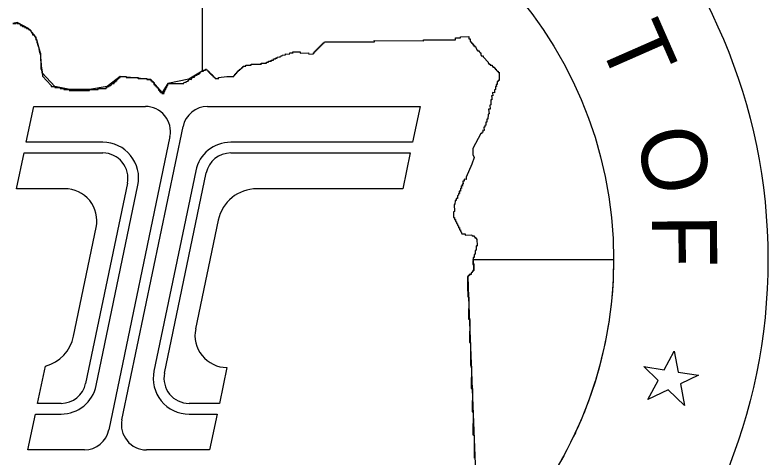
# Model space of a CAD drawing. Extents: x 0 to 1.42, y 0 to 0.92.
# Drawn here: x 1.34592 to 1.37918, y 0.0954 to 0.11497 of the extents above; entities that cross this region are included whole.
import ezdxf

# ---------------------------------------------------------------- set-up
doc = ezdxf.new("R2010")
doc.units = 0
doc.layers.add('P_ODOT_PLAN_TBlock', color=7, linetype='Continuous')

msp = doc.modelspace()

# ---------------------------------------------------------------- linework, layer by layer
at = {"layer": 'P_ODOT_PLAN_TBlock'}
for p, q in [((1.346415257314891, 0.10934955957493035), (1.3467444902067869, 0.11092977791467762)), ((1.3467444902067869, 0.11092977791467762), (1.3516792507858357, 0.11092977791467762)), ((1.35442335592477, 0.11092977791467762), (1.363810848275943, 0.11092977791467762)), ((1.363810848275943, 0.11092977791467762), (1.363481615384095, 0.10934955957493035)), ((1.3506409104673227, 0.09709142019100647), (1.3533404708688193, 0.11004921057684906)), ((1.3527621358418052, 0.10959803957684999), (1.3500626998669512, 0.09664024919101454)), ((1.3497985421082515, 0.10934955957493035), (1.346415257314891, 0.10934955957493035)), ((1.363481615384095, 0.10934955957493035), (1.3554480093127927, 0.10934955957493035)), ((1.345987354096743, 0.10729527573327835), (1.3463165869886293, 0.10887549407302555)), ((1.3463165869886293, 0.10887549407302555), (1.3497985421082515, 0.10887549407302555)), ((1.3554481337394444, 0.10887549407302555), (1.3633828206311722, 0.10887549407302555)), ((1.3633828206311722, 0.10887549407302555), (1.363053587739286, 0.10729527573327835)), ((1.3539010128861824, 0.10809160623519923), (1.352057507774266, 0.09924238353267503)), ((1.3525216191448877, 0.09914570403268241), (1.3543652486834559, 0.10799492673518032)), ((1.3508814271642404, 0.10754375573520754), (1.3490379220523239, 0.09869453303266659)), ((1.3495020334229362, 0.09859785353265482), (1.3513455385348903, 0.10744707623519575)), ((1.3481121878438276, 0.10729527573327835), (1.345987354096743, 0.10729527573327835)), ((1.3481121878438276, 0.10729527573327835), (1.3481121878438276, 0.10729527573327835)), ((1.363053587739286, 0.10729527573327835), (1.3566013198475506, 0.10729527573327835)), ((1.354899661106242, 0.10591152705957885), (1.3538985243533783, 0.10110641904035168)), ((1.3485035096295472, 0.1007779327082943), (1.3495045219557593, 0.10558304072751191)), ((1.3469175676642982, 0.09781396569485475), (1.3472601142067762, 0.09945826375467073)), ((1.3552745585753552, 0.09939754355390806), (1.3549445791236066, 0.09781396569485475)), ((1.3479550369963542, 0.09781396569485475), (1.3469175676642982, 0.09781396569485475)), ((1.3549445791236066, 0.09781396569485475), (1.353604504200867, 0.09781396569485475)), ((1.3464895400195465, 0.09575968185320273), (1.346818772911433, 0.09733990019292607)), ((1.346818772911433, 0.09733990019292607), (1.3479550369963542, 0.09733990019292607)), ((1.353604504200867, 0.09733990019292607), (1.354845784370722, 0.09733990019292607)), ((1.354845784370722, 0.09733990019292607), (1.3545166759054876, 0.09575968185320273)), ((1.3489798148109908, 0.09575968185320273), (1.3464895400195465, 0.09575968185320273)), ((1.3545166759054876, 0.09575968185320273), (1.351723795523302, 0.09575968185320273))]:
    msp.add_line(p, q, dxfattribs=at)
for points in [[(1.3541833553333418, 0.1223454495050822), (1.3541869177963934, 0.1124870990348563), (1.3535949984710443, 0.11213001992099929), (1.3526673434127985, 0.11194921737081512), (1.3524210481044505, 0.11154263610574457), (1.3519121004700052, 0.11212601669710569), (1.3505598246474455, 0.11226013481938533), (1.3499846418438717, 0.11181019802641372), (1.3492117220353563, 0.11167553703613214), (1.348332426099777, 0.11167616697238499), (1.3476754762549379, 0.11181117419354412), (1.3471190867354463, 0.11242080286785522), (1.3470410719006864, 0.11329283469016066), (1.3468748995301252, 0.11387543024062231), (1.346757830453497, 0.1141006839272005), (1.3465189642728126, 0.11436991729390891), (1.3460096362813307, 0.11463941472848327), (1.3458199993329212, 0.1145945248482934)], [(1.3458199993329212, 0.1145945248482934), (1.3459421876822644, 0.11459434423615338), (1.345973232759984, 0.1145932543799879), (1.345973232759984, 0.11463856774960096), (1.3460096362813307, 0.11463941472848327), (1.3460117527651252, 0.11459237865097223), (1.3461239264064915, 0.11459410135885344), (1.3461239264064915, 0.11455110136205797), (1.346162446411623, 0.114550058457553), (1.3461615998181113, 0.11450468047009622), (1.3462373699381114, 0.11450389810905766), (1.3462428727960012, 0.11445858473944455), (1.3463529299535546, 0.11445816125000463), (1.3463394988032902, 0.11441496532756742), (1.3464296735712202, 0.11441502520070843), (1.3464279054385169, 0.11437162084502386), (1.3465189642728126, 0.11436991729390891), (1.3465196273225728, 0.11432449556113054), (1.3465642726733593, 0.11432480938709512), (1.3466109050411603, 0.11428059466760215), (1.3466122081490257, 0.11423561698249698), (1.3466480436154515, 0.1142346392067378), (1.3466477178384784, 0.11418755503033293), (1.346684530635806, 0.11419031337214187), (1.346684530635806, 0.114097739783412), (1.346757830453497, 0.1141006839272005), (1.3467584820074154, 0.1140557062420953), (1.3467936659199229, 0.1140553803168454), (1.3467936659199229, 0.11401117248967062), (1.3468295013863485, 0.11401082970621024), (1.3468402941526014, 0.11387577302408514), (1.3468748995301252, 0.11387543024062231), (1.346874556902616, 0.11374140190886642), (1.3468967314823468, 0.11374018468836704), (1.3469178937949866, 0.11360750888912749), (1.346954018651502, 0.11358414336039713), (1.3470019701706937, 0.11329321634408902), (1.3470410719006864, 0.11329283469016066), (1.3470543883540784, 0.11257532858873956), (1.3471023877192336, 0.11257532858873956), (1.347135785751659, 0.1122662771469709), (1.3475182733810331, 0.11185584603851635), (1.3475204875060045, 0.11181154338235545), (1.3476754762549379, 0.11181117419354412), (1.3476762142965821, 0.11176752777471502), (1.3479095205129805, 0.11176664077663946), (1.347912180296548, 0.11172229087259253), (1.348078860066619, 0.11172051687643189), (1.3480797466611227, 0.11167616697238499), (1.348332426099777, 0.11167616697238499), (1.348315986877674, 0.1116298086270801), (1.3491886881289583, 0.11163307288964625), (1.3492099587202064, 0.11163143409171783), (1.3492117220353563, 0.11167553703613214), (1.3495955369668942, 0.1116796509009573), (1.3495943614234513, 0.11172199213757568), (1.3499399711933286, 0.11172434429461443), (1.3499382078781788, 0.11176962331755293), (1.3499817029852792, 0.11176727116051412), (1.3499846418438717, 0.11181019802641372), (1.350070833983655, 0.11181372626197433), (1.3500704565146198, 0.11185488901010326), (1.350153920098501, 0.11185724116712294), (1.3501586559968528, 0.11190094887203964), (1.3502002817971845, 0.11190198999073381), (1.3502002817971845, 0.11194467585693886), (1.350290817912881, 0.11194519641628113), (1.3502897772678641, 0.11199152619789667), (1.350332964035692, 0.11199152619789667), (1.3503334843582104, 0.11203421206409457), (1.3503829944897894, 0.11204095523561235), (1.350380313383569, 0.11208002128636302), (1.3504240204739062, 0.11208158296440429), (1.3504219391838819, 0.11212687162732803), (1.3504698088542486, 0.11212999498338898), (1.3504698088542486, 0.11217216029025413), (1.3505127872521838, 0.11217370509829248), (1.3505129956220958, 0.11221588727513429), (1.3505557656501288, 0.11221741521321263), (1.3505598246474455, 0.11226013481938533), (1.3508301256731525, 0.11225746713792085), (1.350827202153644, 0.11221505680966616), (1.3513651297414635, 0.11221505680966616), (1.3513629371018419, 0.11216899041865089), (1.3517429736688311, 0.11216899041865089), (1.3517455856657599, 0.11212292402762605), (1.3519121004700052, 0.11212601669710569), (1.3519094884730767, 0.11208093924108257), (1.3519591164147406, 0.11208289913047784), (1.3519525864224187, 0.1120332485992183), (1.352016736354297, 0.1120365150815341), (1.3520156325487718, 0.11199208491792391), (1.3520581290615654, 0.1119894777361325), (1.3520570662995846, 0.11190128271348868), (1.3520989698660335, 0.11190128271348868), (1.352097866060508, 0.1118562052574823), (1.3521409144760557, 0.1118568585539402), (1.3521432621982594, 0.11181236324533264), (1.3521800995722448, 0.11180720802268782), (1.3521817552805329, 0.11176539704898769), (1.3522220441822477, 0.11176997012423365), (1.3522198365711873, 0.11172423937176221), (1.3522628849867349, 0.1117170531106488), (1.3522614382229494, 0.11164577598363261), (1.3522955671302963, 0.1116325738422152), (1.3522995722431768, 0.1115932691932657), (1.3523405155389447, 0.11158854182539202), (1.3523377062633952, 0.11154076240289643), (1.3524210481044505, 0.11154263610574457), (1.3524095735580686, 0.11149757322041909), (1.3525015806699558, 0.11150141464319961), (1.3524843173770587, 0.11158792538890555), (1.3525352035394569, 0.1115977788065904), (1.3525302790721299, 0.11167742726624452), (1.3525754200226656, 0.11168071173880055), (1.3525754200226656, 0.11176939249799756), (1.3526213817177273, 0.11177267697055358), (1.352622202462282, 0.11185889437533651), (1.3526681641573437, 0.11186299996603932), (1.3526673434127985, 0.11194921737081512), (1.353369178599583, 0.11194641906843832), (1.3533879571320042, 0.11199766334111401), (1.3534807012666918, 0.11199437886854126), (1.3534765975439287, 0.11203625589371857), (1.3535660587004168, 0.11204118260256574), (1.3535505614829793, 0.1120827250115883), (1.3535940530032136, 0.11208512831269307), (1.3535949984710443, 0.11213001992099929), (1.3537207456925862, 0.11212907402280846), (1.3537131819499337, 0.11216785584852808), (1.3537477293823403, 0.11217636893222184), (1.3537444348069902, 0.11221988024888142), (1.3538427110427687, 0.11222082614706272), (1.3538436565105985, 0.11225771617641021), (1.3538814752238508, 0.11226826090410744), (1.353882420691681, 0.11230501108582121), (1.3539665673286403, 0.1123156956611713), (1.3539684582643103, 0.1123523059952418), (1.3540461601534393, 0.11235325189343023), (1.354050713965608, 0.11239581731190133), (1.3540904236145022, 0.11240338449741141), (1.3540960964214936, 0.11245257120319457), (1.3541906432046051, 0.1124885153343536), (1.3542435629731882, 0.11248696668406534), (1.3542394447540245, 0.11253063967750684), (1.3543325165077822, 0.1125322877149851), (1.3543308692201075, 0.11257513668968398), (1.3543761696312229, 0.11257596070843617), (1.3543854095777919, 0.11253864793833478), (1.3544247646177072, 0.11252981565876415), (1.3544307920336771, 0.1124904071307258), (1.3544733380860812, 0.11248756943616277), (1.35446955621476, 0.1124412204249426), (1.3545130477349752, 0.11243932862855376), (1.3545121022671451, 0.1123996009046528), (1.3545527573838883, 0.11239487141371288), (1.35455937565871, 0.11235325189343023), (1.3546092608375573, 0.11235136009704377), (1.3546038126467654, 0.11231352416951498), (1.3546504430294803, 0.11230690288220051), (1.3546520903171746, 0.11226149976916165), (1.3546949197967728, 0.11226055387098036), (1.3546957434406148, 0.11222082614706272), (1.3547385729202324, 0.1122160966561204), (1.3547535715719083, 0.11217172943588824), (1.3549156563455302, 0.11217054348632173), (1.3549131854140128, 0.11221751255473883), (1.3552741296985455, 0.11226029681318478), (1.3555915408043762, 0.11226029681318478), (1.3555934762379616, 0.11230676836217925), (1.3556307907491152, 0.11230483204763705), (1.3556315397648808, 0.1123519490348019), (1.3556698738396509, 0.11235130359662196), (1.3556728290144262, 0.11239648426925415), (1.3557134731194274, 0.11239777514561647), (1.3557115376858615, 0.1124410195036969), (1.3557534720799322, 0.11244295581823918), (1.3557502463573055, 0.11248555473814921), (1.3557947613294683, 0.11248942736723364), (1.3557941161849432, 0.11252944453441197), (1.3558516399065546, 0.11253267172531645), (1.3558516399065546, 0.11257591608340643), (1.355892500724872, 0.11257623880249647), (1.355913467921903, 0.11261980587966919), (1.3559534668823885, 0.1126223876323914), (1.355950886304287, 0.11266692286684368), (1.3559960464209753, 0.11266498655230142), (1.3559934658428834, 0.11271016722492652), (1.356110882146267, 0.11271210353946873), (1.3561153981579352, 0.11275470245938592), (1.3563551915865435, 0.11275663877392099), (1.3563551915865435, 0.11280039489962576), (1.3568013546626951, 0.11279927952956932), (1.3567995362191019, 0.11284567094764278), (1.3570219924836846, 0.11284567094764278), (1.35702381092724, 0.11288842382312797), (1.3571126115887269, 0.11288993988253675), (1.357113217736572, 0.11293481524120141), (1.3572471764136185, 0.11293693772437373), (1.357241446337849, 0.1129823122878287), (1.3573349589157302, 0.11298217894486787), (1.3573323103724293, 0.11302816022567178), (1.3574227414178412, 0.1130274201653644), (1.3574168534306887, 0.11307163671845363), (1.3575039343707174, 0.11306926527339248), (1.3575053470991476, 0.1131159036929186), (1.357644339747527, 0.11312027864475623), (1.3576349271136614, 0.11315938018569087), (1.35772579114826, 0.11316254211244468), (1.357720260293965, 0.1132044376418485), (1.3578741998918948, 0.11320958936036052), (1.3578664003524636, 0.11325445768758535), (1.3580475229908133, 0.11324665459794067), (1.3580518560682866, 0.11329867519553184), (1.3581999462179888, 0.1133059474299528), (1.3581982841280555, 0.11333802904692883), (1.3582581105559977, 0.11333942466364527), (1.3585102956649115, 0.11334115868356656), (1.3585163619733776, 0.11329090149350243), (1.358890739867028, 0.11329867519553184), (1.3588942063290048, 0.11324318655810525), (1.3590991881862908, 0.11324958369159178), (1.3590978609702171, 0.11329867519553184), (1.3591420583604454, 0.11329520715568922), (1.359140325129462, 0.11334636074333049), (1.3591819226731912, 0.11334115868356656), (1.3591827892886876, 0.11338711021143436), (1.3592287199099, 0.11338537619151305), (1.3592209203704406, 0.1134304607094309), (1.3592711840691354, 0.11343219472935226), (1.3592670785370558, 0.11347311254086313), (1.3593156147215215, 0.11347630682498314), (1.3593099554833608, 0.11351801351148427), (1.3593600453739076, 0.11352041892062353), (1.3593572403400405, 0.11356451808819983), (1.3594045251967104, 0.11356612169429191), (1.3594021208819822, 0.11360821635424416), (1.3594490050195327, 0.113609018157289), (1.3594466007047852, 0.11365271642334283), (1.3594926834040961, 0.11365351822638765), (1.3594926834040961, 0.11369801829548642), (1.3595371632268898, 0.11369801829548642), (1.3595371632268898, 0.11374251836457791), (1.3595824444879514, 0.11374251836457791), (1.359586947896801, 0.11378814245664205), (1.3618019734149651, 0.11378082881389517), (1.3617847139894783, 0.11384080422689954), (1.3639848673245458, 0.11383658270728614), (1.3639719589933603, 0.11387819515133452), (1.365377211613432, 0.11387617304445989), (1.365378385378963, 0.11396453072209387), (1.3655975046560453, 0.11396701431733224), (1.3655949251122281, 0.11401295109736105), (1.3659632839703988, 0.11401638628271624), (1.3659627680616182, 0.1139232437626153), (1.366025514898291, 0.11392533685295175), (1.3660234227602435, 0.11379765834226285), (1.3660642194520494, 0.11378614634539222), (1.3660782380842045, 0.11374114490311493), (1.3661144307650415, 0.11374428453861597), (1.3661188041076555, 0.11369509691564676), (1.3661531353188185, 0.11369928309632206), (1.366147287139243, 0.11365323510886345), (1.3661939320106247, 0.1136553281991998), (1.366171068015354, 0.11360963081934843), (1.3661827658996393, 0.11361032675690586), (1.3662378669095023, 0.11361032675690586), (1.3662338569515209, 0.11356113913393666), (1.3662776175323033, 0.11356323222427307), (1.366284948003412, 0.11347322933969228), (1.3663137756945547, 0.11347458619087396), (1.3663166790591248, 0.113428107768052), (1.3663511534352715, 0.11343101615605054), (1.3663484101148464, 0.11338298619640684), (1.3664238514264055, 0.11338538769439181), (1.3664207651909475, 0.113337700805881), (1.3664584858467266, 0.11333804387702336), (1.3664631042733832, 0.11329584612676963), (1.3664962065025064, 0.11329447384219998), (1.366501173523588, 0.11320298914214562), (1.3665347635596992, 0.11320414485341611), (1.3665342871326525, 0.11315918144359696), (1.366600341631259, 0.11316178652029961), (1.3665993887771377, 0.1131163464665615), (1.3666207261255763, 0.11311353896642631), (1.3668241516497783, 0.11288765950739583), (1.3668227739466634, 0.11284447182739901), (1.366856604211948, 0.11284523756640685), (1.366856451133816, 0.11280005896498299), (1.3669127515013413, 0.11280098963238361), (1.366916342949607, 0.11275607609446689), (1.3669957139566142, 0.11275643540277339), (1.3669942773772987, 0.11270872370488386), (1.3670327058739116, 0.11271331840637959), (1.3670327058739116, 0.11266804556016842), (1.367096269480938, 0.11266798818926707), (1.3670960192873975, 0.11261971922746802), (1.3671332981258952, 0.11262168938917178), (1.3671317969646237, 0.11257455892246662), (1.367171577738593, 0.11257505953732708), (1.3671695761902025, 0.112529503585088), (1.3672068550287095, 0.11253106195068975), (1.3672211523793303, 0.11248476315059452), (1.3672654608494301, 0.11248771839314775), (1.367269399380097, 0.1124364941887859), (1.3673117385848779, 0.1124394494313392), (1.3673117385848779, 0.11207693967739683), (1.367259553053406, 0.11207890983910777), (1.3672605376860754, 0.11202965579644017), (1.3672162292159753, 0.11203655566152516), (1.3672191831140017, 0.1118986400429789), (1.3671719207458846, 0.11190356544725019), (1.3671876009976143, 0.11180899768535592), (1.3671507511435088, 0.11180899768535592), (1.3671440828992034, 0.11167461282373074), (1.3671041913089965, 0.11166735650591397), (1.3671005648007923, 0.1115381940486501), (1.3670186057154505, 0.11154254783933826), (1.3670222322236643, 0.11140540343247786), (1.366973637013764, 0.11139959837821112), (1.366984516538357, 0.11130599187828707), (1.3669816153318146, 0.11122399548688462), (1.3669344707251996, 0.11122617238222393), (1.3669341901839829, 0.11100103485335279), (1.366889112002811, 0.1109943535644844), (1.3669091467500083, 0.11081729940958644), (1.366842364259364, 0.11081562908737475), (1.3668674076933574, 0.1106001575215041), (1.3668217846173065, 0.1105951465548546), (1.366812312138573, 0.11036631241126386), (1.3667689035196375, 0.11037132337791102), (1.3667622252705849, 0.11023769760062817), (1.3667171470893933, 0.11023769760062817), (1.3667221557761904, 0.11010073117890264), (1.3666737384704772, 0.11009572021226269), (1.3666737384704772, 0.110008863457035), (1.3666370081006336, 0.110008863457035), (1.3666386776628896, 0.109875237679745), (1.3665902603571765, 0.10988525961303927), (1.366591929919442, 0.10979172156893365), (1.366546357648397, 0.10977835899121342), (1.3665451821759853, 0.10974161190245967), (1.3664934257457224, 0.10974161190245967), (1.3661470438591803, 0.10907334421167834), (1.3661470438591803, 0.10881403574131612), (1.3662092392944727, 0.10866882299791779), (1.366105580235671, 0.10837839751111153), (1.365853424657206, 0.10781130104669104), (1.3658548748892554, 0.1077097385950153), (1.3657671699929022, 0.10772569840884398), (1.3657649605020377, 0.10763284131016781), (1.36570840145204, 0.10763284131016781), (1.3657229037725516, 0.10750226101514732), (1.3656750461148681, 0.10749645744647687), (1.365680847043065, 0.10741520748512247), (1.3656300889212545, 0.10741810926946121), (1.3656387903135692, 0.10731219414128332), (1.3655954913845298, 0.10732525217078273), (1.365598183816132, 0.10718161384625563), (1.3655474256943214, 0.1071830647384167), (1.365554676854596, 0.10708730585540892), (1.3655111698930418, 0.10708427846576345), (1.365506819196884, 0.10700605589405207), (1.3654633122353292, 0.10698429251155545), (1.3654618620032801, 0.10686822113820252), (1.365412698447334, 0.10686822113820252), (1.3654033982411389, 0.10678261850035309), (1.365363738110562, 0.1067764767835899), (1.3653548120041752, 0.10660159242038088), (1.3653196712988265, 0.10659719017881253), (1.3653390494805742, 0.10629060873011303), (1.365290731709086, 0.10627587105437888), (1.3652864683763, 0.10602474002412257), (1.3653376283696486, 0.10602616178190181), (1.365336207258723, 0.10593516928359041), (1.3653802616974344, 0.1059323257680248), (1.3653799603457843, 0.10584686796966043), (1.3654271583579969, 0.10583991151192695), (1.3654237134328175, 0.10575856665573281), (1.3654662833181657, 0.10575159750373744), (1.3654639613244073, 0.10566719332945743), (1.3655073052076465, 0.10566099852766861), (1.3655134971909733, 0.10557349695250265), (1.3655491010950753, 0.10557659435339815), (1.3655599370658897, 0.10548676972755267), (1.3655932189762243, 0.10548522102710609), (1.3655932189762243, 0.10540159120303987), (1.365635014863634, 0.10539462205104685), (1.3656512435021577, 0.10530698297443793), (1.3658118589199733, 0.10530521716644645), (1.3658100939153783, 0.10525047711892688), (1.3661030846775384, 0.10526283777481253), (1.3661136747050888, 0.1052204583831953), (1.3662001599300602, 0.1052204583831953), (1.36620368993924, 0.1051763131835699), (1.3662407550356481, 0.10515400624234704), (1.366237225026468, 0.10513169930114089), (1.3662848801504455, 0.1051268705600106), (1.366291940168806, 0.10508272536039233), (1.3663272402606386, 0.10507742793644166), (1.3663325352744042, 0.10476487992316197), (1.366291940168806, 0.10476664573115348), (1.3662937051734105, 0.1045847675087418), (1.3662513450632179, 0.10457417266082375), (1.3662425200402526, 0.10439935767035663), (1.366205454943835, 0.10439623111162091), (1.366205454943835, 0.10426339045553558), (1.3661648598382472, 0.10426162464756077), (1.3661517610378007, 0.1039548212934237), (1.366195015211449, 0.10396046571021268), (1.3661931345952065, 0.10368388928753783), (1.3661508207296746, 0.10368388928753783), (1.3661517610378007, 0.10363779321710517), (1.3661141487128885, 0.10363779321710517), (1.3661103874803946, 0.10359263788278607), (1.3660746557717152, 0.10358678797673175), (1.3660690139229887, 0.10350326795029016), (1.3659872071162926, 0.10350953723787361), (1.3659937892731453, 0.10345811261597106), (1.365944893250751, 0.10345623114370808), (1.3659430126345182, 0.1034138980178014), (1.3659091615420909, 0.10341577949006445), (1.3659145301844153, 0.10300173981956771), (1.3659172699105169, 0.10252206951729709), (1.3659748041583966, 0.102508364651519), (1.365955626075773, 0.10153531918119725), (1.366007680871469, 0.10152161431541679), (1.365992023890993, 0.10049518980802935), (1.3660355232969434, 0.10050389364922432), (1.3660355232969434, 0.09948175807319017), (1.3660842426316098, 0.09946291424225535), (1.3660670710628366, 0.09847609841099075), (1.3661227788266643, 0.09847021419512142), (1.3661203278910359, 0.09743841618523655), (1.3661597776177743, 0.09743653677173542), (1.3661485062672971, 0.09641789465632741), (1.366204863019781, 0.0963915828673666), (1.3661973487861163, 0.0953954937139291)], [(1.3662813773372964, 0.09475265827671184), (1.3659748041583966, 0.102508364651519), (1.3659430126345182, 0.1034138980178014), (1.3661931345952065, 0.10368388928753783), (1.366195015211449, 0.10396046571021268), (1.366160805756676, 0.10416666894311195), (1.3723621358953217, 0.10416666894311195), (1.3723621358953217, 0.10410502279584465), (1.3723621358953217, 0.10399049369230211), (1.3723514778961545, 0.10354586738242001), (1.372343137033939, 0.10333622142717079), (1.3723102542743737, 0.10276577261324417), (1.3722563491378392, 0.10218602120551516), (1.3722485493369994, 0.10207533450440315), (1.3721683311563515, 0.10152062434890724), (1.3721617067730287, 0.10147468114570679), (1.3721618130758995, 0.10147432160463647), (1.3721611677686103, 0.10146936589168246), (1.372150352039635, 0.1013998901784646), (1.3721388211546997, 0.10132640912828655), (1.3721147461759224, 0.10117882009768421), (1.3720970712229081, 0.10107460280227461), (1.3720678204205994, 0.10090914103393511), (1.3720368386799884, 0.1007436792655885), (1.3719958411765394, 0.10053634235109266), (1.3719472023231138, 0.10030554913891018), (1.3718956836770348, 0.10007475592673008), (1.3718212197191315, 0.09976506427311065), (1.3717736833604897, 0.09957910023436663), (1.3717055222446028, 0.09932525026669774), (1.3716391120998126, 0.09909251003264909), (1.3715966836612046, 0.09894732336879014), (1.3715964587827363, 0.0989465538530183), (1.3715941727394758, 0.09893873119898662), (1.371586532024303, 0.0989133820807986), (1.3715217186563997, 0.09870340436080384), (1.3714198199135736, 0.09838987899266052), (1.371299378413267, 0.09804229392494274), (1.3711688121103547, 0.09769127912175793), (1.3710729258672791, 0.09744288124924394), (1.3710150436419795, 0.09729923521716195), (1.3710054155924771, 0.0972756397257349), (1.3709978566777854, 0.09725721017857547), (1.370991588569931, 0.09724197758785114), (1.3709881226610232, 0.0972336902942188), (1.3709876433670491, 0.09723254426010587), (1.3709849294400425, 0.09722584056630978), (1.370972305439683, 0.09719536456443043), (1.3709451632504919, 0.09713097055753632), (1.370811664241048, 0.0968204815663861), (1.3707389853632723, 0.09665809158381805), (1.3706976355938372, 0.09657066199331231), (1.3706741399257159, 0.09651701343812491), (1.370584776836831, 0.09632728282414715), (1.370466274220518, 0.09608390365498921), (1.3703027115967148, 0.09576246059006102), (1.3701531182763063, 0.0954814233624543), (1.37006764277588, 0.09532600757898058)]]:
    msp.add_lwpolyline(points, dxfattribs=at)
msp.add_lwpolyline([(1.3736944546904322, 0.09943832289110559), (1.3745945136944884, 0.09929576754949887), (1.3750436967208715, 0.1001155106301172), (1.3752175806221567, 0.09919708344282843), (1.3761176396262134, 0.09905452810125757), (1.3753172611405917, 0.0986705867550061), (1.3754972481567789, 0.09771992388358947), (1.3747735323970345, 0.09840976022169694), (1.3738720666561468, 0.09797732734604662), (1.3743370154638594, 0.09882584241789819)], close=True, dxfattribs=at)
for radius in [0.025000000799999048, 0.01817878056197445]:
    msp.add_circle((1.3541833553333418, 0.10416666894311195), radius, dxfattribs=at)
for centre, radius, start, end in [((1.3516792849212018, 0.10982358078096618), 0.00110614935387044, 348.23180555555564, 90.00000000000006), ((1.3544233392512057, 0.10982358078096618), 0.00110614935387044, 90.00000000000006, 168.2318055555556), ((1.3497985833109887, 0.10776930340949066), 0.0015802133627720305, 348.23183055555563, 90.00000000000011), ((1.355448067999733, 0.10776930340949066), 0.0015802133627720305, 90.00000000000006, 168.23180000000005), ((1.3497985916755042, 0.10776930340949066), 0.00110614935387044, 348.23171111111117, 90.00000000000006), ((1.3554480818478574, 0.10776930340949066), 0.00110614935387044, 90.00000000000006, 168.23184166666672), ((1.3481122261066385, 0.10587304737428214), 0.0014221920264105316, 348.2317944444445, 90.00000000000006), ((1.3566013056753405, 0.10555700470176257), 0.0017382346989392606, 90.00000000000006, 168.2318944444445), ((1.3552908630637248, 0.10081636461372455), 0.0014221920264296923, 168.23179444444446, 269.30883611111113), ((1.3468017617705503, 0.10113240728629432), 0.0017382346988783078, 285.46915555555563, 348.23171111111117), ((1.353604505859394, 0.09892010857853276), 0.0015802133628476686, 168.23183055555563, 270.0000000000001), ((1.3536045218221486, 0.09892010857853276), 0.001106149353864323, 168.2317944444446, 270.00000000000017), ((1.347955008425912, 0.09892010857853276), 0.0011061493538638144, 270.00000000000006, 348.2317722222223), ((1.3479550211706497, 0.09892010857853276), 0.0015802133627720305, 270.00000000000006, 348.2318), ((1.3517238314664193, 0.09686583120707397), 0.0011061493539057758, 168.2317694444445, 270.00000000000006), ((1.348979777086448, 0.09686583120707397), 0.00110614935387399, 270.00000000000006, 348.23175555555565)]:
    msp.add_arc(centre, radius, start, end, dxfattribs=at)

# ---------------------------------------------------------------- texts
for s, rotation, p in [('T', 293.7296823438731, (1.371654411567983, 0.11384904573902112)), ('O', 281.0153190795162, (1.3733570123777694, 0.10976641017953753)), ('F', 270.4549130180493, (1.37405852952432, 0.10615756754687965))]:
    msp.add_text(s, height=0.0028694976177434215, rotation=rotation, dxfattribs=at).set_placement(p)

doc.saveas('drawing.dxf')
